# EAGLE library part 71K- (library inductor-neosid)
TRANSFORMER adjustable filter transformer, type K
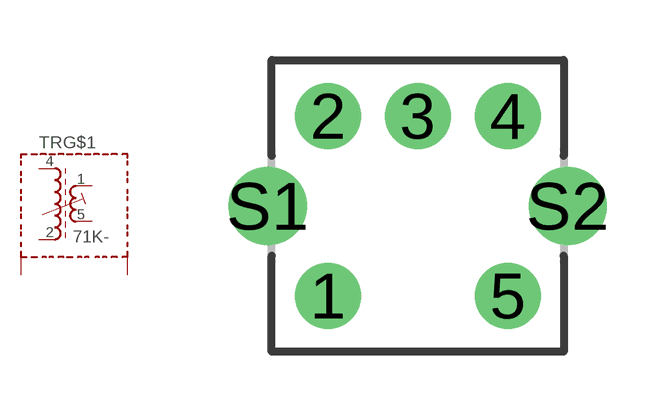
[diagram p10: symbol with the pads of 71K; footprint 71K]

Designator prefix TR; gates G$1=SMF51-3 G$2=SHIELD3

## 71K-4215 (OC_FARNELL: unknown; OC_NEWARK: unknown)  [71K]
1  G$1:A2  pas
2  G$1:E1  pas
4  G$1:A1  pas
5  G$1:E2  pas
S1  G$2:S1  pas
S2  G$2:S2  pas

## 71K-1542 (OC_FARNELL: unknown; OC_NEWARK: unknown)  [71K]
1  G$1:A1  pas
2  G$1:A2  pas
4  G$1:E2  pas
5  G$1:E1  pas
S1  G$2:S1  pas
S2  G$2:S2  pas

## 71K-2451 (OC_FARNELL: unknown; OC_NEWARK: unknown)  [71K]
1  G$1:E2  pas
2  G$1:A1  pas
4  G$1:E1  pas
5  G$1:A2  pas
S1  G$2:S1  pas
S2  G$2:S2  pas

## 71K-4251 (OC_FARNELL: unknown; OC_NEWARK: unknown)  [71K]
1  G$1:E2  pas
2  G$1:E1  pas
4  G$1:A1  pas
5  G$1:A2  pas
S1  G$2:S1  pas
S2  G$2:S2  pas

## 71K-2315 (OC_FARNELL: unknown; OC_NEWARK: unknown)  [71K]
1  G$1:A2  pas
2  G$1:A1  pas
3  G$1:E1  pas
5  G$1:E2  pas
S1  G$2:S1  pas
S2  G$2:S2  pas

## 71K-5142 (OC_FARNELL: unknown; OC_NEWARK: unknown)  [71K]
1  G$1:E1  pas
2  G$1:E2  pas
4  G$1:A2  pas
5  G$1:A1  pas
S1  G$2:S1  pas
S2  G$2:S2  pas

## 71K-5412 (OC_FARNELL: unknown; OC_NEWARK: unknown)  [71K]
1  G$1:A2  pas
2  G$1:E2  pas
4  G$1:E1  pas
5  G$1:A1  pas
S1  G$2:S1  pas
S2  G$2:S2  pas

## 71K-1524 (OC_FARNELL: unknown; OC_NEWARK: unknown)  [71K]
Pads as for 71K

## 71K-2143 (OC_FARNELL: unknown; OC_NEWARK: unknown)  [71K]
1  G$1:E1  pas
2  G$1:A1  pas
3  G$1:E2  pas
4  G$1:A2  pas
S1  G$2:S1  pas
S2  G$2:S2  pas

## 71K-5123 (OC_FARNELL: unknown; OC_NEWARK: unknown)  [71K]
1  G$1:E1  pas
2  G$1:A2  pas
3  G$1:E2  pas
5  G$1:A1  pas
S1  G$2:S1  pas
S2  G$2:S2  pas

## 71K-5241 (OC_FARNELL: unknown; OC_NEWARK: unknown)  [71K]
1  G$1:E2  pas
2  G$1:E1  pas
4  G$1:A2  pas
5  G$1:A1  pas
S1  G$2:S1  pas
S2  G$2:S2  pas

## 71K-4512 (OC_FARNELL: unknown; OC_NEWARK: unknown)  [71K]
1  G$1:A2  pas
2  G$1:E2  pas
4  G$1:A1  pas
5  G$1:E1  pas
S1  G$2:S1  pas
S2  G$2:S2  pas

## 71K-1532 (OC_FARNELL: unknown; OC_NEWARK: unknown)  [71K]
1  G$1:A1  pas
2  G$1:E2  pas
3  G$1:A2  pas
5  G$1:E1  pas
S1  G$2:S1  pas
S2  G$2:S2  pas

## 71K-3254 (OC_FARNELL: unknown; OC_NEWARK: unknown)  [71K]
2  G$1:E1  pas
3  G$1:A1  pas
4  G$1:E2  pas
5  G$1:A2  pas
S1  G$2:S1  pas
S2  G$2:S2  pas

## 71K-2415 (OC_FARNELL: unknown; OC_NEWARK: unknown)  [71K]
1  G$1:A2  pas
2  G$1:A1  pas
4  G$1:E1  pas
5  G$1:E2  pas
S1  G$2:S1  pas
S2  G$2:S2  pas

## Footprint 71K (pad centres in mm)
RF COIL ASSEMBLY 1 winding, 5 pads, grid 2.25 mm
drill 1.1 round: 1 -2.25,-2.25; 2 -2.25,2.25; 3 0,2.25; 4 2.25,2.25; 5 2.25,-2.25
drill 1.3 round: S1 -3.75,0; S2 3.75,0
